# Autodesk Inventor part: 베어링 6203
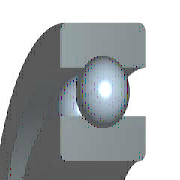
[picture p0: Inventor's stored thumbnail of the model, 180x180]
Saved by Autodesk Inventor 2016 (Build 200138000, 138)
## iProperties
Created: 2012-02
Part Number: 베어링 6203
Material: 강철, 연강
Description: 깊은 그루브 볼 베어링
Document SubType Name: Modeling
Standard: KS B 2023
Designer: mduedu
Standards Organization: KS
Language: ko-KR
Size Designation: 6203 - 17 x 40 x 12
Categories: <MemberInstance><Categories><Category DisplayName="샤프트 부품" InternalName="7f7aeb1f-a693-4053-b835-cee3144e0d98" Mnemonic="SHFT"><Category DisplayName="베어링" Inter
Density: 1 g/cm^3
Appearance: 노란색
IsCustomPart: 1
Author: mduedu
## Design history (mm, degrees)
sketch "스케치" dims "d0" = 5.98 (= -0.26 x WD + 0.26 x BD)
  geometry: L1 (3.01, 14.25)-(8.99, 14.25); L2 (6, 14.25)-(6, 11.26); L3 (6, 14.25)-(6, 17.24); L4 (3.778, 12.249)-(0, 12.249); L5 (0, 8.5)-(12, 8.5); L6 (3.778, 16.251)-(0, 16.251); L7 (0, 20)-(12, 20); L8 (12, 8.5)-(12, 12.249); L9 (8.222, 12.249)-(12, 12.249); L10 (8.222, 16.251)-(12, 16.251); L11 (12, 20)-(12, 16.251); L12 (-1.4, 0)-(8.4, 0) reference; L13 (0, -0.3)-(0, 5.3) reference
  constraints: 22 end point, 4 point on line, 2 collinear, 2 perpendicular, 2 symmetric about line, 1 midpoint, 1 parallel, 14 other
  dimensions: "d9" = 17 diameter of L5 L12 (= WD); "d11" = 40 diameter of L7 L12 (= BD); "d12" = 12 distance between parallel lines of L8 L13 (= KB); "d13" = 24.498 diameter of L9 L12 (= 0.326 x BD + 0.674 x WD)
revolve "본체" stored, may be unused: angle "d6" = 90 deg
revolve "볼" stored, may be unused: angle "d7" = 90 deg
pattern_circular "IDS_ARRAYBALL[SIMPL:T]" dims angle "d3" = 360 deg
body "Solid1"
fillet "모깎기1" dims "d1" = 0.6 (= KRS)
other parameters: "WD" = 17 [user parameter; used in 5 equation terms], "BD" = 40 [user parameter; used in 5 equation terms], "KB" = 12 [user parameter; used in 1 equation term], "KRS" = 0.6 [user parameter; used in 1 equation term], "d4" = 0, "d5" = 0, "d8" = 0, "d14" = 0, "d15" = 0, "BBA" = 0 [user parameter], "BC0" = 4750000 [user parameter], "BC" = 9560000 [user parameter], "WR" = 8.5 (= 0.5 x WD) [user parameter]
